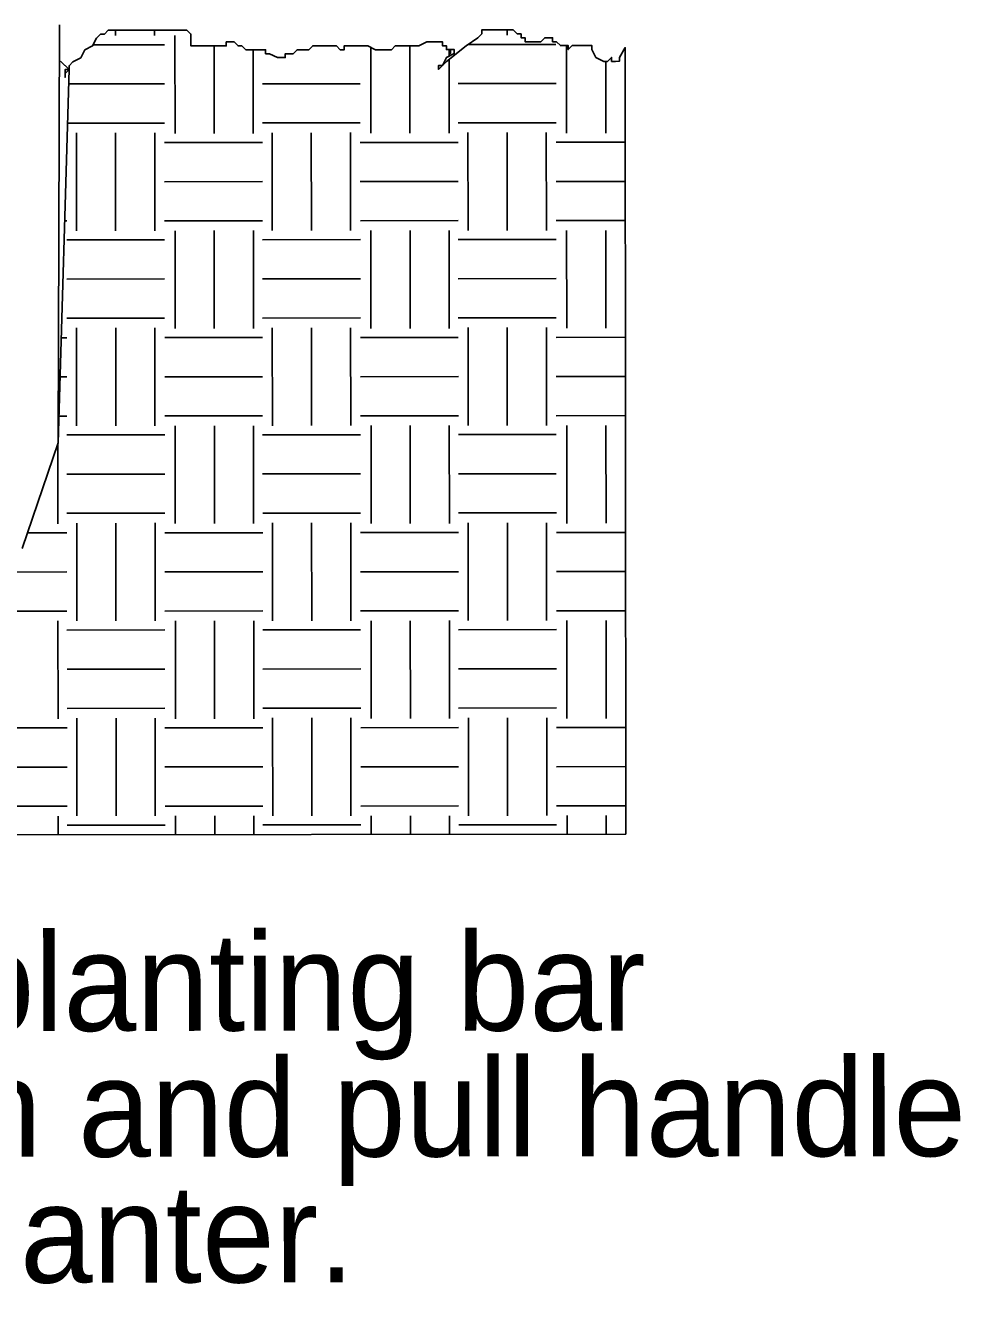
# Model space of a CAD drawing. Extents: x 1728110 to 1729925, y 1284214 to 1285339.
# Drawn here: x 1728681.8 to 1728747.6, y 1284892.4 to 1284982.9 of the extents above; entities that cross this region are included whole.
import ezdxf

# ---------------------------------------------------------------- set-up
doc = ezdxf.new("R2010")
doc.units = 0
doc.layers.add('Reforestation Detail CELL', color=7, linetype='Continuous')

msp = doc.modelspace()

# ---------------------------------------------------------------- linework, layer by layer
at = {"layer": 'Reforestation Detail CELL'}
for p, q in [((1728684.21, 1284983.017), (1728684.111, 1284953.591)), ((1728688.154, 1284982.631), (1728688.153, 1284982.252)), ((1728690.909, 1284982.633), (1728690.909, 1284982.254)), ((1728715.712, 1284982.651), (1728715.713, 1284982.272)), ((1728686.589, 1284981.61), (1728691.599, 1284981.613)), ((1728692.338, 1284982.254), (1728692.344, 1284975.365)), ((1728695.095, 1284981.527), (1728695.099, 1284975.367)), ((1728706.119, 1284981.432), (1728706.123, 1284975.375)), ((1728708.874, 1284981.537), (1728708.879, 1284975.378)), ((1728712.962, 1284981.629), (1728719.158, 1284981.633)), ((1728719.898, 1284981.546), (1728719.903, 1284975.386)), ((1728697.851, 1284981.253), (1728697.855, 1284975.369)), ((1728711.631, 1284981.263), (1728711.631, 1284980.801)), ((1728711.631, 1284980.58), (1728711.635, 1284975.38)), ((1728724.077, 1284926.037), (1728724.036, 1284981.411)), ((1728684.884, 1284979.858), (1728684.111, 1284953.591)), ((1728684.279, 1284980.463), (1728684.884, 1284979.858)), ((1728722.656, 1284980.441), (1728722.659, 1284975.388)), ((1728684.854, 1284978.853), (1728691.601, 1284978.857)), ((1728698.491, 1284978.862), (1728705.38, 1284978.868)), ((1728712.27, 1284978.872), (1728719.16, 1284978.878)), ((1728684.773, 1284976.097), (1728691.603, 1284976.101)), ((1728698.493, 1284976.107), (1728705.383, 1284976.111)), ((1728712.272, 1284976.117), (1728719.162, 1284976.122)), ((1728685.403, 1284975.407), (1728685.408, 1284968.518)), ((1728688.158, 1284975.41), (1728688.164, 1284968.52)), ((1728690.914, 1284975.412), (1728690.92, 1284968.522)), ((1728699.182, 1284975.419), (1728699.187, 1284968.528)), ((1728701.938, 1284975.42), (1728701.943, 1284968.531)), ((1728704.694, 1284975.422), (1728704.699, 1284968.533)), ((1728712.962, 1284975.429), (1728712.967, 1284968.539)), ((1728715.718, 1284975.43), (1728715.723, 1284968.541)), ((1728718.474, 1284975.432), (1728718.479, 1284968.543)), ((1728691.604, 1284974.724), (1728698.494, 1284974.729)), ((1728705.383, 1284974.734), (1728712.274, 1284974.739)), ((1728719.163, 1284974.744), (1728724.04, 1284974.747)), ((1728684.652, 1284971.962), (1728684.716, 1284971.962)), ((1728691.607, 1284971.968), (1728698.496, 1284971.973)), ((1728705.386, 1284971.978), (1728712.276, 1284971.983)), ((1728719.165, 1284971.988), (1728724.042, 1284971.992)), ((1728684.571, 1284969.206), (1728684.719, 1284969.207)), ((1728691.608, 1284969.212), (1728698.498, 1284969.217)), ((1728705.388, 1284969.222), (1728712.277, 1284969.227)), ((1728719.168, 1284969.232), (1728724.044, 1284969.236)), ((1728684.72, 1284967.877), (1728691.609, 1284967.882)), ((1728692.348, 1284968.523), (1728692.355, 1284961.634)), ((1728695.105, 1284968.526), (1728695.11, 1284961.635)), ((1728697.86, 1284968.528), (1728697.866, 1284961.637)), ((1728698.499, 1284967.887), (1728705.389, 1284967.892)), ((1728706.128, 1284968.534), (1728706.133, 1284961.644)), ((1728708.884, 1284968.536), (1728708.889, 1284961.646)), ((1728711.64, 1284968.538), (1728711.645, 1284961.648)), ((1728712.279, 1284967.897), (1728719.168, 1284967.902)), ((1728719.908, 1284968.544), (1728719.913, 1284961.654)), ((1728722.664, 1284968.546), (1728722.669, 1284961.657)), ((1728698.501, 1284965.131), (1728705.39, 1284965.137)), ((1728712.281, 1284965.141), (1728719.17, 1284965.147)), ((1728684.721, 1284965.121), (1728691.612, 1284965.126)), ((1728684.724, 1284962.365), (1728691.614, 1284962.37)), ((1728685.413, 1284961.676), (1728685.419, 1284954.787)), ((1728688.17, 1284961.679), (1728688.174, 1284954.789)), ((1728690.925, 1284961.681), (1728690.93, 1284954.79)), ((1728698.503, 1284962.375), (1728705.393, 1284962.38)), ((1728699.192, 1284961.687), (1728699.198, 1284954.797)), ((1728701.948, 1284961.689), (1728701.953, 1284954.799)), ((1728704.704, 1284961.691), (1728704.709, 1284954.802)), ((1728712.282, 1284962.386), (1728719.173, 1284962.39)), ((1728712.972, 1284961.697), (1728712.977, 1284954.807)), ((1728715.728, 1284961.699), (1728715.733, 1284954.81)), ((1728718.484, 1284961.701), (1728718.489, 1284954.812)), ((1728684.329, 1284960.987), (1728684.724, 1284960.987)), ((1728691.615, 1284960.992), (1728698.504, 1284960.997)), ((1728705.394, 1284961.003), (1728712.284, 1284961.008)), ((1728719.173, 1284961.013), (1728724.051, 1284961.016)), ((1728684.247, 1284958.231), (1728684.726, 1284958.231)), ((1728691.617, 1284958.236), (1728698.506, 1284958.242)), ((1728705.396, 1284958.247), (1728712.286, 1284958.252)), ((1728719.175, 1284958.257), (1728724.053, 1284958.261)), ((1728684.167, 1284955.475), (1728684.729, 1284955.475)), ((1728691.618, 1284955.48), (1728698.508, 1284955.486)), ((1728705.398, 1284955.491), (1728712.288, 1284955.496)), ((1728719.178, 1284955.501), (1728724.054, 1284955.505)), ((1728692.36, 1284954.792), (1728692.365, 1284947.902)), ((1728695.116, 1284954.794), (1728695.121, 1284947.904)), ((1728697.871, 1284954.797), (1728697.877, 1284947.906)), ((1728706.138, 1284954.802), (1728706.143, 1284947.913)), ((1728708.894, 1284954.805), (1728708.899, 1284947.915)), ((1728711.65, 1284954.807), (1728711.655, 1284947.916)), ((1728719.918, 1284954.813), (1728719.923, 1284947.923)), ((1728722.674, 1284954.815), (1728722.679, 1284947.925)), ((1728684.111, 1284953.591), (1728681.587, 1284946.157)), ((1728684.111, 1284953.591), (1728681.587, 1284946.157)), ((1728684.093, 1284953.534), (1728684.097, 1284947.896)), ((1728684.73, 1284954.145), (1728691.62, 1284954.151)), ((1728698.509, 1284954.156), (1728705.399, 1284954.161)), ((1728712.289, 1284954.166), (1728719.178, 1284954.171)), ((1728684.731, 1284951.389), (1728691.622, 1284951.395)), ((1728698.511, 1284951.4), (1728705.402, 1284951.405)), ((1728712.291, 1284951.41), (1728719.18, 1284951.416)), ((1728684.734, 1284948.634), (1728691.624, 1284948.639)), ((1728685.424, 1284947.945), (1728685.429, 1284941.056)), ((1728688.18, 1284947.947), (1728688.185, 1284941.058)), ((1728690.936, 1284947.95), (1728690.941, 1284941.059)), ((1728698.513, 1284948.644), (1728705.403, 1284948.649)), ((1728699.202, 1284947.955), (1728699.209, 1284941.066)), ((1728701.959, 1284947.958), (1728701.964, 1284941.068)), ((1728704.714, 1284947.96), (1728704.72, 1284941.069)), ((1728712.293, 1284948.654), (1728719.183, 1284948.659)), ((1728712.982, 1284947.966), (1728712.987, 1284941.076)), ((1728715.738, 1284947.968), (1728715.743, 1284941.078)), ((1728718.494, 1284947.97), (1728718.499, 1284941.081)), ((1728681.959, 1284947.254), (1728684.735, 1284947.256)), ((1728691.625, 1284947.261), (1728698.514, 1284947.266)), ((1728705.404, 1284947.271), (1728712.294, 1284947.277)), ((1728719.184, 1284947.282), (1728724.061, 1284947.285)), ((1728677.847, 1284944.495), (1728684.737, 1284944.5)), ((1728691.627, 1284944.505), (1728698.516, 1284944.51)), ((1728705.406, 1284944.515), (1728712.296, 1284944.521)), ((1728719.186, 1284944.526), (1728724.063, 1284944.529)), ((1728677.849, 1284941.739), (1728684.739, 1284941.744)), ((1728691.629, 1284941.749), (1728698.519, 1284941.754)), ((1728705.408, 1284941.759), (1728712.298, 1284941.765)), ((1728719.188, 1284941.77), (1728724.065, 1284941.774)), ((1728684.102, 1284941.054), (1728684.107, 1284934.165)), ((1728692.37, 1284941.061), (1728692.375, 1284934.17)), ((1728695.126, 1284941.063), (1728695.131, 1284934.173)), ((1728697.882, 1284941.064), (1728697.887, 1284934.175)), ((1728706.149, 1284941.071), (1728706.155, 1284934.181)), ((1728708.904, 1284941.073), (1728708.911, 1284934.183)), ((1728711.661, 1284941.076), (1728711.666, 1284934.185)), ((1728719.928, 1284941.081), (1728719.933, 1284934.192)), ((1728722.684, 1284941.084), (1728722.689, 1284934.194)), ((1728684.74, 1284940.414), (1728691.63, 1284940.419)), ((1728698.519, 1284940.424), (1728705.409, 1284940.43)), ((1728712.299, 1284940.435), (1728719.189, 1284940.44)), ((1728684.743, 1284937.658), (1728691.632, 1284937.663)), ((1728698.522, 1284937.669), (1728705.412, 1284937.674)), ((1728712.301, 1284937.679), (1728719.191, 1284937.684)), ((1728684.744, 1284934.902), (1728691.634, 1284934.907)), ((1728698.524, 1284934.913), (1728705.414, 1284934.918)), ((1728712.303, 1284934.923), (1728719.193, 1284934.928)), ((1728677.856, 1284933.52), (1728684.745, 1284933.525)), ((1728685.434, 1284934.214), (1728685.439, 1284927.325)), ((1728688.19, 1284934.216), (1728688.195, 1284927.327)), ((1728690.946, 1284934.218), (1728690.951, 1284927.328)), ((1728691.635, 1284933.53), (1728698.525, 1284933.535)), ((1728699.214, 1284934.224), (1728699.219, 1284927.335)), ((1728701.969, 1284934.226), (1728701.975, 1284927.337)), ((1728704.726, 1284934.229), (1728704.73, 1284927.338)), ((1728705.415, 1284933.54), (1728712.304, 1284933.545)), ((1728712.992, 1284934.234), (1728712.998, 1284927.345)), ((1728715.748, 1284934.237), (1728715.753, 1284927.347)), ((1728718.504, 1284934.239), (1728718.509, 1284927.349)), ((1728719.194, 1284933.55), (1728724.071, 1284933.554)), ((1728677.857, 1284930.764), (1728684.748, 1284930.769)), ((1728691.637, 1284930.774), (1728698.526, 1284930.779)), ((1728705.417, 1284930.784), (1728712.306, 1284930.789)), ((1728719.196, 1284930.794), (1728724.073, 1284930.798)), ((1728677.859, 1284928.008), (1728684.75, 1284928.013)), ((1728691.639, 1284928.018), (1728698.529, 1284928.023)), ((1728705.419, 1284928.028), (1728712.308, 1284928.033)), ((1728719.198, 1284928.039), (1728724.075, 1284928.043)), ((1728684.112, 1284927.323), (1728684.113, 1284926.007)), ((1728692.38, 1284927.33), (1728692.381, 1284926.013)), ((1728695.136, 1284927.332), (1728695.137, 1284926.015)), ((1728697.892, 1284927.333), (1728697.893, 1284926.018)), ((1728706.16, 1284927.34), (1728706.16, 1284926.023)), ((1728708.916, 1284927.342), (1728708.917, 1284926.026)), ((1728711.671, 1284927.344), (1728711.673, 1284926.028)), ((1728719.938, 1284927.35), (1728719.94, 1284926.034)), ((1728722.694, 1284927.352), (1728722.695, 1284926.037)), ((1728684.75, 1284926.683), (1728691.64, 1284926.688)), ((1728698.53, 1284926.693), (1728705.42, 1284926.698)), ((1728712.31, 1284926.704), (1728719.199, 1284926.709)), ((1728642.174, 1284925.976), (1728724.077, 1284926.037))]:
    msp.add_line(p, q, dxfattribs=at)
for points in [[(1728684.279, 1284980.463), (1728684.33, 1284980.412), (1728684.884, 1284979.858), (1728684.608, 1284979.858), (1728684.608, 1284979.581), (1728684.608, 1284979.305), (1728684.608, 1284979.581), (1728684.884, 1284979.858), (1728684.884, 1284980.135), (1728685.161, 1284980.413), (1728685.714, 1284980.691), (1728685.99, 1284981.244), (1728686.543, 1284981.521), (1728686.82, 1284982.076), (1728687.095, 1284982.352), (1728687.372, 1284982.352), (1728687.649, 1284982.63), (1728687.926, 1284982.63), (1728688.202, 1284982.63), (1728688.756, 1284982.631), (1728689.034, 1284982.631), (1728689.586, 1284982.632), (1728689.863, 1284982.631), (1728690.14, 1284982.632), (1728690.416, 1284982.632), (1728690.693, 1284982.632), (1728690.969, 1284982.633), (1728691.8, 1284982.634), (1728692.076, 1284982.633), (1728692.353, 1284982.633), (1728692.63, 1284982.634), (1728692.906, 1284982.634), (1728693.184, 1284982.634), (1728693.46, 1284982.356), (1728693.46, 1284981.803), (1728693.461, 1284981.526), (1728693.738, 1284981.526), (1728694.291, 1284981.527), (1728694.844, 1284981.527), (1728695.121, 1284981.527), (1728695.398, 1284981.527), (1728695.674, 1284981.528), (1728695.952, 1284981.528), (1728695.951, 1284981.804), (1728696.227, 1284981.805), (1728696.504, 1284981.805), (1728696.781, 1284981.528), (1728697.058, 1284981.529), (1728697.335, 1284981.253), (1728697.612, 1284981.253), (1728697.887, 1284981.253), (1728698.166, 1284981.253), (1728698.442, 1284981.253), (1728698.718, 1284981.253), (1728698.718, 1284980.976), (1728698.995, 1284980.976), (1728699.548, 1284980.701), (1728699.825, 1284980.701), (1728700.103, 1284980.701), (1728700.102, 1284980.977), (1728700.379, 1284980.977), (1728700.656, 1284980.977), (1728700.932, 1284981.255), (1728701.208, 1284981.255), (1728701.485, 1284981.256), (1728701.763, 1284981.256), (1728702.038, 1284981.533), (1728702.593, 1284981.533), (1728702.869, 1284981.533), (1728703.145, 1284981.533), (1728703.422, 1284981.533), (1728703.699, 1284981.534), (1728703.977, 1284981.257), (1728704.252, 1284981.258), (1728704.252, 1284981.534), (1728704.529, 1284981.535), (1728704.805, 1284981.535), (1728705.083, 1284981.535), (1728705.359, 1284981.535), (1728705.635, 1284981.535), (1728705.912, 1284981.535), (1728706.465, 1284981.259), (1728706.743, 1284981.26), (1728707.019, 1284981.259), (1728707.296, 1284981.26), (1728707.573, 1284981.26), (1728707.849, 1284981.537), (1728708.125, 1284981.537), (1728708.404, 1284981.537), (1728708.68, 1284981.537), (1728708.956, 1284981.538), (1728709.51, 1284981.538), (1728710.062, 1284981.815)], [(1728710.062, 1284981.815), (1728709.51, 1284981.538), (1728708.956, 1284981.538), (1728708.68, 1284981.537), (1728708.404, 1284981.537), (1728708.125, 1284981.537), (1728707.849, 1284981.537), (1728707.573, 1284981.26), (1728707.296, 1284981.26), (1728707.019, 1284981.259), (1728706.743, 1284981.26), (1728706.465, 1284981.259), (1728705.912, 1284981.535), (1728705.635, 1284981.535), (1728705.359, 1284981.535), (1728705.083, 1284981.535), (1728704.805, 1284981.535), (1728704.529, 1284981.535), (1728704.252, 1284981.534), (1728704.252, 1284981.258), (1728703.977, 1284981.257), (1728703.699, 1284981.534), (1728703.422, 1284981.533), (1728703.145, 1284981.533), (1728702.869, 1284981.533), (1728702.593, 1284981.533), (1728702.038, 1284981.533), (1728701.763, 1284981.256), (1728701.485, 1284981.256), (1728701.208, 1284981.255), (1728700.932, 1284981.255), (1728700.656, 1284980.977), (1728700.379, 1284980.977), (1728700.102, 1284980.977), (1728700.103, 1284980.701), (1728699.825, 1284980.701), (1728699.548, 1284980.701), (1728698.995, 1284980.976), (1728698.718, 1284980.976), (1728698.718, 1284981.253), (1728698.442, 1284981.253), (1728698.166, 1284981.253), (1728697.887, 1284981.253), (1728697.612, 1284981.253), (1728697.335, 1284981.253), (1728697.058, 1284981.529), (1728696.781, 1284981.528), (1728696.504, 1284981.805), (1728696.227, 1284981.805), (1728695.951, 1284981.804), (1728695.952, 1284981.528), (1728695.674, 1284981.528), (1728695.398, 1284981.527), (1728695.121, 1284981.527), (1728694.844, 1284981.527), (1728694.291, 1284981.527), (1728693.738, 1284981.526), (1728693.461, 1284981.526), (1728693.46, 1284981.803), (1728693.46, 1284982.356), (1728693.184, 1284982.634), (1728692.906, 1284982.634), (1728692.63, 1284982.634), (1728692.353, 1284982.633), (1728692.076, 1284982.633), (1728691.8, 1284982.634), (1728690.969, 1284982.633), (1728690.693, 1284982.632), (1728690.416, 1284982.632), (1728690.14, 1284982.632), (1728689.863, 1284982.631), (1728689.586, 1284982.632), (1728689.034, 1284982.631), (1728688.756, 1284982.631), (1728688.202, 1284982.63), (1728687.926, 1284982.63), (1728687.649, 1284982.63), (1728687.372, 1284982.352), (1728687.095, 1284982.352), (1728686.82, 1284982.076), (1728686.543, 1284981.521), (1728685.99, 1284981.244), (1728685.714, 1284980.691), (1728685.161, 1284980.413), (1728684.884, 1284980.135), (1728684.884, 1284979.858), (1728684.608, 1284979.581), (1728684.608, 1284979.305), (1728684.608, 1284979.581), (1728684.608, 1284979.858), (1728684.884, 1284979.858), (1728684.33, 1284980.412), (1728684.279, 1284980.463)], [(1728710.062, 1284981.815), (1728710.616, 1284981.815), (1728710.893, 1284981.815), (1728711.17, 1284981.816), (1728711.17, 1284981.539), (1728711.446, 1284981.54), (1728711.446, 1284981.263), (1728711.446, 1284981.54), (1728711.446, 1284981.263), (1728711.723, 1284981.263), (1728711.723, 1284980.986), (1728711.723, 1284981.263), (1728712.001, 1284981.263), (1728712.001, 1284980.986), (1728711.447, 1284980.71), (1728711.171, 1284980.156), (1728710.894, 1284980.156), (1728710.894, 1284979.878), (1728711.448, 1284980.432), (1728712.829, 1284981.541), (1728713.659, 1284982.095), (1728713.936, 1284982.372), (1728713.935, 1284982.649), (1728714.213, 1284982.65), (1728714.766, 1284982.65), (1728715.042, 1284982.651), (1728715.32, 1284982.651), (1728715.596, 1284982.651), (1728715.873, 1284982.652), (1728716.149, 1284982.651), (1728716.426, 1284982.374), (1728716.703, 1284982.374), (1728716.703, 1284982.098), (1728716.981, 1284982.098), (1728716.981, 1284981.821), (1728717.257, 1284981.82), (1728717.534, 1284981.82), (1728718.087, 1284981.821), (1728718.363, 1284982.099), (1728718.64, 1284982.099), (1728718.918, 1284982.099), (1728718.918, 1284981.822), (1728719.194, 1284981.821), (1728719.471, 1284981.546), (1728719.747, 1284981.546), (1728720.025, 1284981.546), (1728720.025, 1284981.27), (1728720.301, 1284981.547), (1728720.578, 1284981.547), (1728720.853, 1284981.546), (1728721.132, 1284981.546), (1728721.407, 1284981.547), (1728721.685, 1284981.547), (1728721.685, 1284981.271), (1728721.962, 1284980.718), (1728722.516, 1284980.441), (1728722.792, 1284980.44), (1728723.068, 1284980.718), (1728723.068, 1284980.441), (1728723.346, 1284980.441), (1728723.621, 1284980.442), (1728723.621, 1284980.719), (1728724.036, 1284981.411), (1728724.036, 1284981.411)], [(1728724.036, 1284981.411), (1728724.036, 1284981.411), (1728723.621, 1284980.719), (1728723.621, 1284980.442), (1728723.346, 1284980.441), (1728723.068, 1284980.441), (1728723.068, 1284980.718), (1728722.792, 1284980.44), (1728722.516, 1284980.441), (1728721.962, 1284980.718), (1728721.685, 1284981.271), (1728721.685, 1284981.547), (1728721.407, 1284981.547), (1728721.132, 1284981.546), (1728720.853, 1284981.546), (1728720.578, 1284981.547), (1728720.301, 1284981.547), (1728720.025, 1284981.27), (1728720.025, 1284981.546), (1728719.747, 1284981.546), (1728719.471, 1284981.546), (1728719.194, 1284981.821), (1728718.918, 1284981.822), (1728718.918, 1284982.099), (1728718.64, 1284982.099), (1728718.363, 1284982.099), (1728718.087, 1284981.821), (1728717.534, 1284981.82), (1728717.257, 1284981.82), (1728716.981, 1284981.821), (1728716.981, 1284982.098), (1728716.703, 1284982.098), (1728716.703, 1284982.374), (1728716.426, 1284982.374), (1728716.149, 1284982.651), (1728715.873, 1284982.652), (1728715.596, 1284982.651), (1728715.32, 1284982.651), (1728715.042, 1284982.651), (1728714.766, 1284982.65), (1728714.213, 1284982.65), (1728713.935, 1284982.649), (1728713.936, 1284982.372), (1728713.659, 1284982.095), (1728712.829, 1284981.541), (1728711.448, 1284980.432), (1728710.894, 1284979.878), (1728710.894, 1284980.156), (1728711.171, 1284980.156), (1728711.447, 1284980.71), (1728712.001, 1284980.986), (1728712.001, 1284981.263), (1728711.723, 1284981.263), (1728711.723, 1284980.986), (1728711.723, 1284981.263), (1728711.446, 1284981.263), (1728711.446, 1284981.54), (1728711.446, 1284981.263), (1728711.446, 1284981.54), (1728711.17, 1284981.539), (1728711.17, 1284981.816), (1728710.893, 1284981.815), (1728710.616, 1284981.815), (1728710.062, 1284981.815)]]:
    msp.add_lwpolyline(points, dxfattribs=at)

# ---------------------------------------------------------------- texts
for s, p in [('1. Insert planting bar ', (1728641.478, 1284912.165)), (' as shown and pull handle ', (1728641.484, 1284903.307)), (' toward planter.', (1728641.491, 1284894.449))]:
    msp.add_text(s, height=6.88975, rotation=0.04293, dxfattribs=at).set_placement(p)

doc.saveas('drawing.dxf')
